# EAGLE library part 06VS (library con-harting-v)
CONNECTOR
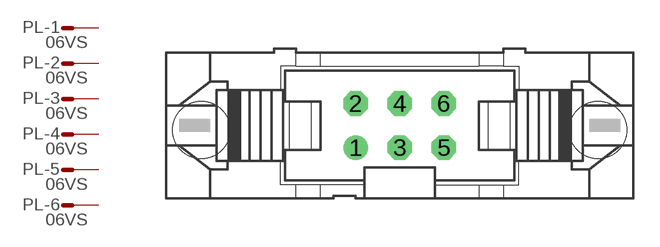
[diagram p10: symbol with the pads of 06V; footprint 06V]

Designator prefix PL; gates -1=M -2=M -3=M -4=M -5=M -6=M

## 06VS (OC_FARNELL: unknown; OC_NEWARK: unknown)  [06V]
1  -1:S  pas
2  -2:S  pas
3  -3:S  pas
4  -4:S  pas
5  -5:S  pas
6  -6:S  pas

## Footprint 06V (pad centres in mm)
CONNECTOR
drill 0.914 round: 1 -2.54,-1.27
drill 0.914 octagon: 2 -2.54,1.27; 3 0,-1.27; 4 0,1.27; 5 2.54,-1.27; 6 2.54,1.27
hole 3.302 at 11.43,-0.254
hole 3.302 at -11.43,-0.254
